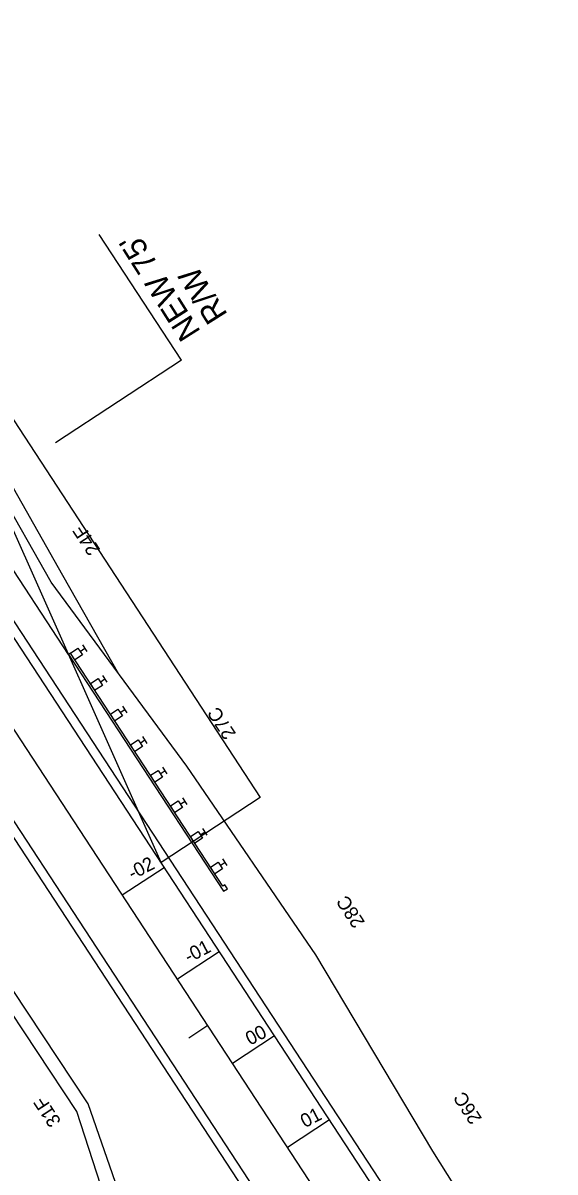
# Model space of a CAD drawing. Extents: x 1551641 to 1624343, y 1119533 to 1136600.
# Drawn here: x 1552738.3 to 1552854.9, y 1134049.4 to 1134301 of the extents above; entities that cross this region are included whole.
import ezdxf

# ---------------------------------------------------------------- set-up
doc = ezdxf.new("R2010")
doc.units = 0
for name, color, linetype in [('Prop CMT Pvmt Surface', 7, 'Continuous'), ('RD_HC_Data_Tic', 7, 'Continuous'), ('RD_Sketch1', 7, 'Continuous'), ('RD_XS_Base', 7, 'Continuous'), ('RD_XS_EarthShd', 7, 'Continuous'), ('RD_XS_ExPaveRet', 7, 'Continuous'), ('RD_XS_Pave', 7, 'Continuous'), ('RD_XS_TieSlope', 7, 'Continuous'), ('RD_XS_TX_Elev_EX', 7, 'Continuous'), ('RD_XS_TX_Slope', 7, 'Continuous'), ('Scratch_Level_0', 7, 'Continuous')]:
    doc.layers.add(name, color=color, linetype=linetype)

msp = doc.modelspace()

# ---------------------------------------------------------------- linework, layer by layer
at = {"layer": 'Prop CMT Pvmt Surface'}
for p, q in [((1552760.1, 1134110.09), (1552769.3, 1134116.12)), ((1552772.16, 1134091.69), (1552781.36, 1134097.72)), ((1552784.22, 1134073.29), (1552793.42, 1134079.32)), ((1552796.27, 1134054.89), (1552805.47, 1134060.92))]:
    msp.add_line(p, q, dxfattribs=at)
at = {"layer": 'RD_HC_Data_Tic'}
msp.add_line((1552778.84, 1134081.5), (1552774.65, 1134078.76), dxfattribs=at)
at = {"layer": 'RD_Sketch1'}
for p, q in [((1552843.32, 1134006.81), (1552718.03, 1134198.02)), ((1552821.57, 1133992.56), (1552697.38, 1134182.1))]:
    msp.add_line(p, q, dxfattribs=at)
at = {"layer": 'RD_XS_Base'}
for p, q in [((1552748.3, 1134162.77), (1552713.11, 1134216.47)), ((1552752.4, 1134163.36), (1552751.44, 1134164.82)), ((1552748.72, 1134163.04), (1552748.3, 1134162.77)), ((1552748.3, 1134162.77), (1552782.28, 1134110.91)), ((1552748.72, 1134163.04), (1552750.39, 1134164.14)), ((1552749.68, 1134161.58), (1552748.72, 1134163.04)), ((1552782.15, 1134112.02), (1552748.72, 1134163.04)), ((1552751.35, 1134162.67), (1552749.68, 1134161.58)), ((1552750.39, 1134164.14), (1552751.35, 1134162.67)), ((1552750.87, 1134163.41), (1552751.92, 1134164.09)), ((1552753.1, 1134156.35), (1552754.78, 1134157.45)), ((1552754.78, 1134157.45), (1552755.74, 1134155.98)), ((1552755.26, 1134156.71), (1552756.3, 1134157.4)), ((1552756.78, 1134156.67), (1552755.82, 1134158.13)), ((1552754.06, 1134154.89), (1552753.1, 1134156.35)), ((1552755.74, 1134155.98), (1552754.06, 1134154.89)), ((1552757.49, 1134149.66), (1552759.16, 1134150.75)), ((1552758.45, 1134148.19), (1552757.49, 1134149.66)), ((1552759.16, 1134150.75), (1552760.12, 1134149.29)), ((1552759.64, 1134150.02), (1552760.69, 1134150.71)), ((1552761.17, 1134149.98), (1552760.21, 1134151.44)), ((1552760.12, 1134149.29), (1552758.45, 1134148.19)), ((1552765.55, 1134143.28), (1552764.59, 1134144.75)), ((1552761.87, 1134142.97), (1552763.55, 1134144.06)), ((1552762.83, 1134141.5), (1552761.87, 1134142.97)), ((1552764.51, 1134142.6), (1552762.83, 1134141.5)), ((1552763.55, 1134144.06), (1552764.51, 1134142.6)), ((1552764.03, 1134143.33), (1552765.07, 1134144.02)), ((1552766.26, 1134136.28), (1552767.93, 1134137.37)), ((1552767.93, 1134137.37), (1552768.89, 1134135.91)), ((1552768.41, 1134136.64), (1552769.46, 1134137.32)), ((1552769.94, 1134136.59), (1552768.98, 1134138.06)), ((1552767.22, 1134134.81), (1552766.26, 1134136.28)), ((1552768.89, 1134135.91), (1552767.22, 1134134.81)), ((1552770.64, 1134129.58), (1552772.32, 1134130.68)), ((1552771.6, 1134128.12), (1552770.64, 1134129.58)), ((1552772.32, 1134130.68), (1552773.27, 1134129.22)), ((1552772.8, 1134129.95), (1552773.84, 1134130.63)), ((1552774.32, 1134129.9), (1552773.36, 1134131.37)), ((1552773.27, 1134129.22), (1552771.6, 1134128.12)), ((1552778.7, 1134123.21), (1552777.75, 1134124.67)), ((1552775.03, 1134122.89), (1552776.7, 1134123.99)), ((1552775.99, 1134121.43), (1552775.03, 1134122.89)), ((1552777.66, 1134122.52), (1552775.99, 1134121.43)), ((1552776.7, 1134123.99), (1552777.66, 1134122.52)), ((1552777.18, 1134123.26), (1552778.23, 1134123.94)), ((1552779.41, 1134116.2), (1552781.08, 1134117.3)), ((1552781.08, 1134117.3), (1552782.04, 1134115.83)), ((1552781.56, 1134116.57), (1552782.61, 1134117.25)), ((1552783.09, 1134116.52), (1552782.13, 1134117.98)), ((1552780.37, 1134114.74), (1552779.41, 1134116.2)), ((1552782.04, 1134115.83), (1552780.37, 1134114.74)), ((1552782.57, 1134112.29), (1552782.15, 1134112.02)), ((1552783.12, 1134111.46), (1552782.57, 1134112.29)), ((1552782.28, 1134110.91), (1552783.12, 1134111.46))]:
    msp.add_line(p, q, dxfattribs=at)
at = {"layer": 'RD_XS_EarthShd'}
for p, q in [((1552841.65, 1134005.71), (1552481.59, 1134555.23)), ((1552823.24, 1133993.65), (1552463.19, 1134543.17))]:
    msp.add_line(p, q, dxfattribs=at)
at = {"layer": 'RD_XS_ExPaveRet'}
for p, q in [((1552747.11, 1134180.04), (1552722.35, 1134223.65)), ((1552759.37, 1134158.41), (1552747.11, 1134180.04)), ((1552750.16, 1134062.69), (1552722.56, 1134104.25)), ((1552765.93, 1134014.08), (1552750.16, 1134062.69))]:
    msp.add_line(p, q, dxfattribs=at)
at = {"layer": 'RD_XS_Pave'}
for q in [(1552755.02, 1134254.69), (1552745.46, 1134209.07)]:
    msp.add_line((1552773.06, 1134227.16), q, dxfattribs=at)
at = {"layer": 'RD_XS_TieSlope'}
for p, q in [((1552702.65, 1134265.28), (1552790.34, 1134131.45)), ((1552768.59, 1134117.2), (1552702.65, 1134265.28)), ((1552790.34, 1134131.45), (1552768.59, 1134117.2))]:
    msp.add_line(p, q, dxfattribs=at)
at = {"layer": 'RD_XS_TX_Elev_EX'}
for p, q in [((1552744.5, 1134178.56), (1552719.76, 1134222.13)), ((1552774.24, 1134138.26), (1552744.5, 1134178.56)), ((1552802.49, 1134097), (1552774.24, 1134138.26)), ((1552752.66, 1134064.35), (1552725, 1134106)), ((1552828.13, 1134054.02), (1552802.49, 1134097)), ((1552769.61, 1134015.68), (1552752.66, 1134064.35)), ((1552854.91, 1134011.71), (1552828.13, 1134054.02))]:
    msp.add_line(p, q, dxfattribs=at)
at = {"layer": 'Scratch_Level_0'}
msp.add_line((1552832.44, 1133999.68), (1552472.39, 1134549.2), dxfattribs=at)

# ---------------------------------------------------------------- texts
at = {"layer": 'Prop CMT Pvmt Surface'}
for s, p in [('-02', (1552762.33, 1134113.3)), ('-01', (1552774.66, 1134095.09)), ('00', (1552788.09, 1134077.07)), ('01', (1552800.12, 1134059.01))]:
    msp.add_text(s, height=3, rotation=27.7864, dxfattribs=at).set_placement(p)
at = {"layer": 'RD_XS_Pave'}
for s, p in [("NEW 75' ", (1552777.39, 1134233.42)), ('R/W', (1552783.3, 1134237.16))]:
    msp.add_text(s, height=5, rotation=122.3587, dxfattribs=at).set_placement(p)
at = {"layer": 'RD_XS_TX_Slope'}
for s, p in [('24F', (1552755.37, 1134185.68)), ('27C', (1552785.11, 1134145.39)), ('28C', (1552813.36, 1134104.12)), ('26C', (1552839, 1134061.15)), ('31F', (1552746.8, 1134060.51))]:
    msp.add_text(s, height=3, rotation=123.2337, dxfattribs=at).set_placement(p)

doc.saveas('drawing.dxf')
